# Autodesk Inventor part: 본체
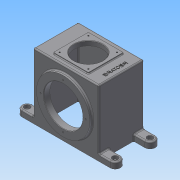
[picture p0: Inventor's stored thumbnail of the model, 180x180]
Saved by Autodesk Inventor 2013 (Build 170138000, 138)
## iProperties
Created: 2016-11
Part Number: 본체
Material: 알루미늄 6061
Document SubType Name: Modeling
Designer: mduedu
Density: 2.71 g/cm^3
Mass: 2143.26 g
Surface Area: 1967.93 cm^2
Volume: 790.871 cm^3
Author: mduedu
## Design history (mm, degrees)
sketch "스케치1"
  geometry: L1 (-80, 0)-(80, 0); L2 (80, 0)-(80, 160); L3 (80, 160)-(-80, 160); L4 (-80, 160)-(-80, 0); 2 further points
  constraints: 8 end point, 2 parallel, 1 coincident, 1 horizontal, 1 midpoint, 1 perpendicular
  dimensions: "d0" = 160 distance of L2.end L3.end; "d2" = 160 distance of L1.end L2.end
extrude "돌출1" new body sketch "스케치1" stored distance "d3" = 110; taper "d4" = 0 deg
sketch "스케치2"
  geometry: L1 (-80, -55)-(-80, 55) reference; L2 (-80, -55)-(-120, -55); L3 (-120, -55)-(-120, 55); L4 (-120, 55)-(-80, 55); L5 (-80, 55)-(-80, -55); 1 further point
  constraints: 8 end point, 2 parallel, 1 horizontal, 1 perpendicular
  dimensions: "d5" = 40 distance of L1.end L3.end
extrude "돌출2" join sketch "스케치2" distance "d6" = 15; taper "d7" = 0 deg
sketch "스케치3"
  geometry: L1 (80, 55)-(80, -55) reference; L2 (120, -55)-(120, 55) reference; L3 (80, 30)-(120, 30); L4 (120, 30)-(120, -30); L5 (120, -30)-(80, -30); L6 (80, -30)-(80, 30); L7 (-80, -55)-(120, -55) reference; L8 (-80, 55)-(120, 55) reference; 1 further point
  constraints: 8 end point, 2 parallel, 2 point on line, 1 horizontal, 1 perpendicular
  dimensions: "d8" = 25 distance between parallel lines of L5 L7; "d9" = 25 distance between parallel lines of L3 L8 (= d8)
extrude "돌출3" cut sketch "스케치3" stored distance "d10" = 15; taper "d11" = 0 deg
fillet "모깎기1"
fillet "모깎기2"
hole "구멍1" diameter "d14" = 9; stored, may be unused: countersink angle "d18" = 90 deg, drill point angle "d20" = 118 deg; dims "d12" = 10, "d13" = 10, "d15" = 6, "d16" = 14, "d17" = 8, "d19" = 8
fillet "모깎기3" dims "d21" = 3
fillet "모깎기4" dims "d22" = 3
sketch "스케치4"
  geometry: L1 (80, 160)-(-80, 160) reference; L2 (-80, 17.196)-(-80, 160) reference; L3 (80, 17.196)-(80, 160) reference; L4 (-72, 0)-(-72, 152); L5 (-72, 152)-(72, 152); L6 (72, 152)-(72, 0); L7 (-72, 0)-(72, 0); 2 further points
  constraints: 8 end point, 1 coincident, 1 midpoint, 1 perpendicular
  dimensions: "d23" = 8 distance between parallel lines of L5 L1; "d24" = 8 distance between parallel lines of L3 L6 (= d23); "d25" = 8 distance between parallel lines of L2 L4 (= d23)
extrude "돌출4" cut sketch "스케치4" stored distance "d26" = 94; taper "d27" = 0 deg
fillet "모깎기5" dims "d28" = 3
fillet "모깎기6" dims "d29" = 3
fillet "모깎기7" dims "d30" = 3
fillet "모깎기8" dims "d31" = 3
sketch "스케치5"
  geometry: C1 r 65 at (0, 80); 1 further point
  constraints: 1 centre point, 1 vertical alignment
  dimensions: "d32" = 130 diameter of C1; "d33" = 80 distance of C1.centre point (0, 0)
extrude "돌출5" join sketch "스케치5" distance "d34" = 7; taper "d35" = 0 deg
sketch "스케치6"
  geometry: C1 r 35 at (77, 51.5); 2 further points
  constraints: 1 centre point, 1 coincident, 1 vertical alignment
  dimensions: "d36" = 70 diameter of C1; "d77" = 0.5 distance of point (77, 52) point (77, 51.5)
extrude "돌출6" cut sketch "스케치6" stored distance "d37" = 7; taper "d38" = 0 deg
sketch "스케치7"
  geometry: L1 (34.5, 9)-(119.5, 9); L2 (119.5, 9)-(119.5, 94); L3 (119.5, 94)-(34.5, 94); L4 (34.5, 94)-(34.5, 9); L5 (34.5, 9)-(119.5, 94); L6 (119.5, 9)-(34.5, 94); C1 r 35 at (77, 51.5) reference; 2 further points
  constraints: 12 end point, 3 midpoint, 2 parallel, 1 coincident, 1 horizontal, 1 perpendicular
  dimensions: "d39" = 85 distance of L3.end L2.end; "d40" = 85 distance of L1.end L2.end (= d39)
extrude "돌출7" join sketch "스케치7" distance "d41" = 3; taper "d42" = 0 deg
fillet "모깎기9" dims "d43" = 3
fillet "모깎기10" dims "d44" = 2
hole "구멍2" diameter "d47" = 95; stored, may be unused: countersink angle "d51" = 90 deg, drill point angle "d53" = 118 deg; dims "d45" = 10, "d46" = 10, "d48" = 6, "d49" = 14, "d50" = 8, "d52" = 8
chamfer "모따기1" distance "d54" = 1; stored, may be unused: second distance "d55" = 2, angle "d56" = 45 deg
sketch "스케치8"
  geometry: C1 r 65 at (0, 80) reference; C2 r 31.5 at (0, 80); 1 further point
  constraints: 1 centre point, 1 coincident
  dimensions: "d57" = 63 diameter of C2
extrude "돌출8" join sketch "스케치8" distance "d58" = 14; taper "d59" = 0 deg
hole "구멍3" diameter "d62" = 30; stored, may be unused: countersink angle "d66" = 90 deg, drill point angle "d68" = 0 deg; dims "d60" = 10, "d61" = 10, "d63" = 6, "d64" = 47, "d65" = 14, "d67" = 17
fillet "모깎기11" dims "d69" = 3
fillet "모깎기12" dims "d70" = 3
fillet "모깎기13" dims "d71" = 0.5
chamfer "모따기2" distance "d72" = 1; stored, may be unused: second distance "d73" = 2, angle "d74" = 45 deg
fillet "모깎기14" dims "d75" = 3
sketch "스케치9"
  geometry: L1 (157, 0)-(157, 104) reference; L2 (77, 52)-(157, 52); 1 further point
  constraints: 2 end point, 1 midpoint, 1 point on line, 1 other
  dimensions: "d78" = 65 distance of point (142, 52) L2.start
feature "엠보싱1" sketch "스케치9" dims "d79" = 0.5, "d80" = 0
sketch "스케치10"
  geometry: 4 further points
  constraints: 4 other
hole "구멍4" sketch "스케치10" at (0, -55), (55, 0), (-55, 0), (0, 55) diameter "d81" = 3.242; stored, may be unused: countersink angle "d85" = 90 deg, drill point angle "d87" = 120 deg; dims "d82" = 6.6, "d83" = 4, "d84" = 2, "d86" = 8.6
sketch "스케치11"
  geometry: 4 further points
  constraints: 4 other
hole "구멍5" sketch "스케치11" at (42, 86.5), (112, 86.5), (112, 16.5), (42, 16.5) diameter "d88" = 3.242; stored, may be unused: countersink angle "d92" = 90 deg, drill point angle "d94" = 120 deg; dims "d89" = 6.6, "d90" = 4, "d91" = 2, "d93" = 8.6
node "솔리드1"
mirror "대칭1"
mirror "대칭2"
mirror "대칭3"
